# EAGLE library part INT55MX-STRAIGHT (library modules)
CT (05/03/2008): rename bpl-module to int55mx-straight
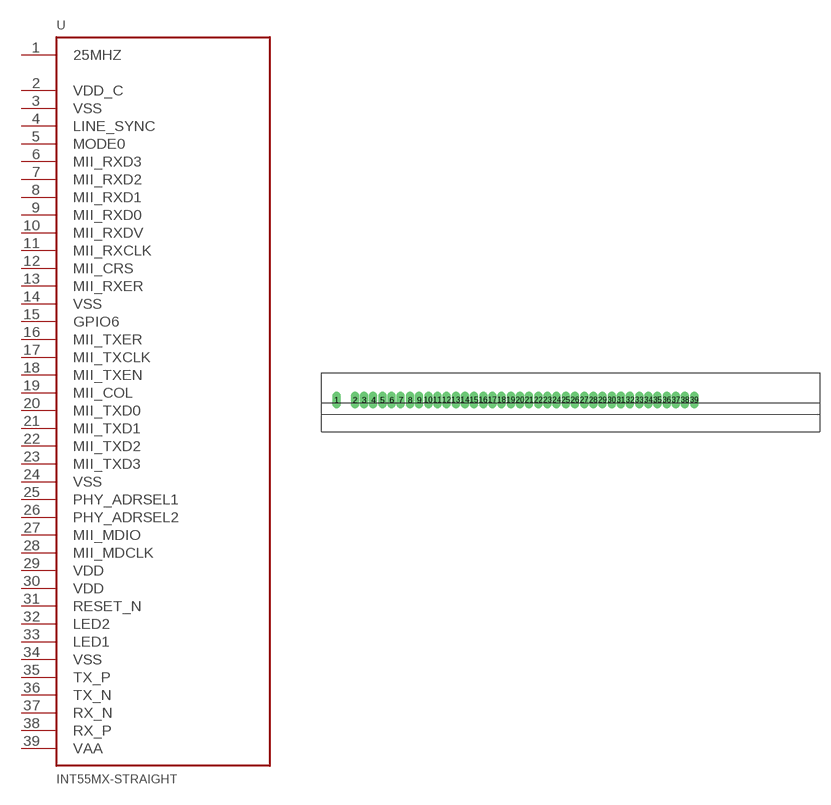
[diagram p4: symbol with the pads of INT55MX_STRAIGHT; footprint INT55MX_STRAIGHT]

Designator prefix U

## INT55MX-STRAIGHT  [INT55MX_STRAIGHT]
1  25MHZ
2  VDD_C
3  VSS
4  LINE_SYNC
5  MODE0
6  MII_RXD3
7  MII_RXD2
8  MII_RXD1
9  MII_RXD0
10  MII_RXDV
11  MII_RXCLK
12  MII_CRS
13  MII_RXER
14  VSS
15  GPIO6
16  MII_TXER
17  MII_TXCLK
18  MII_TXEN
19  MII_COL
20  MII_TXD0
21  MII_TXD1
22  MII_TXD2
23  MII_TXD3
24  VSS
25  PHY_ADRSEL1
26  PHY_ADRSEL2
27  MII_MDIO
28  MII_MDCLK
29  VDD
30  VDD
31  RESET_N
32  LED2
33  LED1
34  VSS
35  TX_P
36  TX_N
37  RX_N
38  RX_P
39  VAA

## Footprint INT55MX_STRAIGHT (pad centres in mm)
drill 0.7 pad 1.016 long: 1 -29.69,0.57; 2 -27.15,0.57; 3 -25.88,0.57; 4 -24.61,0.57; 5 -23.34,0.57; 6 -22.06,0.57; 7 -20.79,0.57; 8 -19.52,0.57; 9 -18.25,0.57; 10 -16.98,0.57; 11 -15.71,0.57; 12 -14.44,0.57; 13 -13.17,0.57; 14 -11.9,0.57; 15 -10.63,0.57; 16 -9.36,0.57; 17 -8.09,0.57; 18 -6.81,0.57; 19 -5.54,0.57; 20 -4.27,0.57; 21 -3,0.57; 22 -1.73,0.57; 23 -0.46,0.57; 24 0.81,0.57; 25 2.08,0.57; 26 3.35,0.57; 27 4.62,0.57; 28 5.89,0.57; 29 7.16,0.57; 30 8.44,0.57; 31 9.71,0.57; 32 10.98,0.57; 33 12.25,0.57; 34 13.52,0.57; 35 14.79,0.57; 36 16.06,0.57; 37 17.33,0.57; 38 18.6,0.57; 39 19.87,0.57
